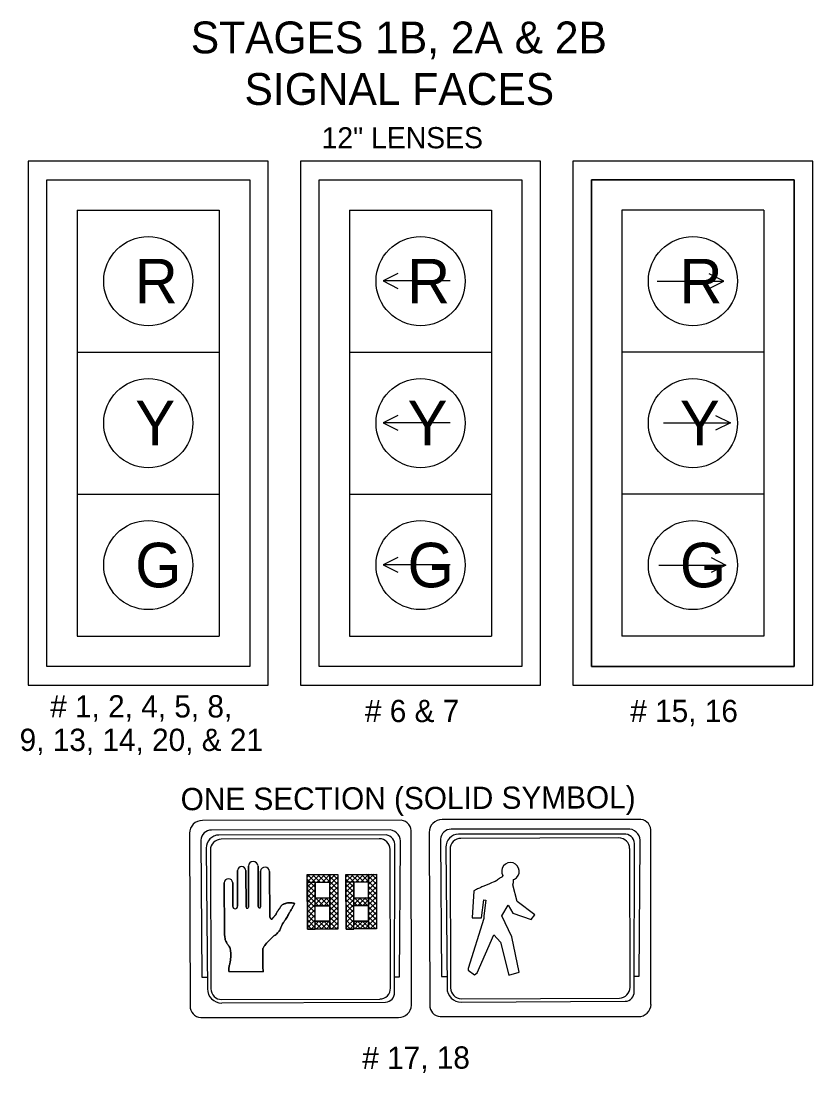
# Model space of a CAD drawing. Extents: x -218554 to 420030, y -566264 to -483460.
# Drawn here: x 418346.3 to 418495.6, y -565507.2 to -565308.8 of the extents above; entities that cross this region are included whole.
import ezdxf

# ---------------------------------------------------------------- set-up
doc = ezdxf.new("R2010")
doc.units = 0
for name, color, linetype in [('G-ANNO-STMP', 7, 'Continuous'), ('G-Border-Paper', 7, 'Continuous'), ('Level 1', 7, 'Continuous'), ('Level 61', 7, 'Continuous')]:
    doc.layers.add(name, color=color, linetype=linetype)

msp = doc.modelspace()

# ---------------------------------------------------------------- linework, layer by layer
at = {"layer": 'G-Border-Paper'}
for points in [[(418347.6, -565335.25), (418347.6, -565434.06), (418392.9, -565434.06), (418392.9, -565335.25), (418347.6, -565335.25)], [(418398.97, -565335.25), (418398.97, -565434.06), (418444.27, -565434.06), (418444.27, -565335.25), (418398.97, -565335.25)], [(418450.34, -565335.25), (418450.34, -565434.06), (418495.64, -565434.06), (418495.64, -565335.25), (418450.34, -565335.25)], [(418351.13, -565430.55), (418351.13, -565338.75), (418389.39, -565338.75), (418389.39, -565430.55), (418351.13, -565430.55)], [(418402.5, -565430.55), (418402.5, -565338.75), (418440.75, -565338.75), (418440.75, -565430.55), (418402.5, -565430.55)], [(418453.87, -565430.55), (418453.87, -565338.75), (418492.12, -565338.75), (418492.12, -565430.55), (418453.87, -565430.55)]]:
    msp.add_lwpolyline(points, dxfattribs=at)
at = {"layer": 'Level 1'}
for p, q in [((418417.97, -565459.55), (418380.47, -565459.58)), ((418463.18, -565459.4), (418425.68, -565459.43)), ((418378.02, -565462.02), (418378.16, -565494.56)), ((418415.91, -565461.37), (418382.19, -565461.41)), ((418419.88, -565494.44), (418419.84, -565461.93)), ((418423.23, -565461.86), (418423.37, -565494.4)), ((418461.11, -565461.22), (418427.39, -565461.26)), ((418460.34, -565462.18), (418428.79, -565462.18)), ((418465.08, -565494.28), (418465.05, -565461.77)), ((418415.14, -565462.33), (418383.59, -565462.34)), ((418381.19, -565464.82), (418381.41, -565491.33)), ((418416.71, -565492.01), (418416.75, -565464.45)), ((418426.39, -565464.66), (418426.62, -565491.18)), ((418461.92, -565491.86), (418461.95, -565464.29)), ((418390.97, -565468.19), (418390.99, -565475.85)), ((418390.99, -565475.85), (418390.97, -565468.19)), ((418387.1, -565475.79), (418387.07, -565469.05)), ((418387.07, -565469.05), (418387.1, -565475.79)), ((418388.67, -565469.06), (418388.7, -565475.9)), ((418388.7, -565475.9), (418388.67, -565469.06)), ((418389.16, -565475.93), (418389.13, -565468.21)), ((418389.13, -565468.21), (418389.16, -565475.93)), ((418391.45, -565475.89), (418391.43, -565469.16)), ((418391.43, -565469.16), (418391.45, -565475.89)), ((418393.14, -565469.21), (418393.17, -565477.87)), ((418393.17, -565477.87), (418393.14, -565469.21)), ((418400.23, -565472.19), (418402.62, -565469.78)), ((418400.23, -565470.27), (418400.71, -565469.79)), ((418400.23, -565471.23), (418401.66, -565469.79)), ((418400.28, -565469.79), (418401.79, -565471.29)), ((418401.24, -565469.79), (418402.75, -565471.28)), ((418402.08, -565471.29), (418403.58, -565469.78)), ((418402.2, -565469.79), (418403.7, -565471.28)), ((418403.04, -565471.28), (418404.53, -565469.78)), ((418403.15, -565469.78), (418406.01, -565472.62)), ((418403.99, -565471.28), (418405.49, -565469.77)), ((418404.11, -565469.78), (418406, -565471.66)), ((418405.07, -565469.78), (418406, -565470.7)), ((418407.52, -565470.25), (418408, -565469.77)), ((418407.53, -565471.2), (418408.96, -565469.76)), ((418407.53, -565472.16), (418409.91, -565469.76)), ((418407.58, -565469.77), (418409.08, -565471.26)), ((418408.54, -565469.76), (418410.04, -565471.26)), ((418409.38, -565471.26), (418410.87, -565469.76)), ((418409.49, -565469.76), (418411, -565471.26)), ((418410.33, -565471.26), (418411.83, -565469.75)), ((418410.45, -565469.76), (418413.3, -565472.59)), ((418411.29, -565471.25), (418412.78, -565469.75)), ((418411.41, -565469.75), (418413.3, -565471.63)), ((418412.36, -565469.75), (418413.3, -565470.68)), ((418384.61, -565480.66), (418384.58, -565471.34)), ((418384.58, -565471.34), (418384.61, -565480.66)), ((418386.18, -565471.35), (418386.19, -565475.8)), ((418386.19, -565475.8), (418386.18, -565471.35)), ((418400.23, -565470.69), (418401.73, -565472.19)), ((418400.23, -565471.65), (418401.74, -565473.14)), ((418400.24, -565473.14), (418401.73, -565471.64)), ((418404.5, -565471.73), (418406, -565470.22)), ((418404.51, -565472.68), (418406, -565471.18)), ((418404.51, -565472.08), (418406.01, -565473.57)), ((418404.51, -565473.64), (418406.01, -565472.13)), ((418407.52, -565470.67), (418409.03, -565472.16)), ((418407.53, -565473.12), (418409.03, -565471.61)), ((418407.53, -565471.62), (418409.03, -565473.12)), ((418411.8, -565471.7), (418413.29, -565470.2)), ((418411.8, -565472.66), (418413.3, -565471.15)), ((418411.8, -565472.05), (418413.31, -565473.55)), ((418411.81, -565473.61), (418413.3, -565472.11)), ((418439.32, -565470.67), (418439.32, -565470.67)), ((418400.24, -565474.1), (418401.74, -565472.59)), ((418400.24, -565472.61), (418403.33, -565475.68)), ((418400.24, -565475.06), (418401.74, -565473.55)), ((418400.24, -565473.56), (418402.38, -565475.69)), ((418403.44, -565475.68), (418406.01, -565473.09)), ((418404.39, -565475.68), (418406.01, -565474.05)), ((418404.51, -565473.04), (418406.01, -565474.53)), ((418404.51, -565473.99), (418406.02, -565475.49)), ((418407.53, -565472.58), (418410.63, -565475.66)), ((418407.53, -565473.54), (418409.67, -565475.66)), ((418407.54, -565474.07), (418409.03, -565472.57)), ((418407.54, -565475.03), (418409.03, -565473.53)), ((418407.54, -565475.99), (418409.36, -565474.16)), ((418407.55, -565476.94), (418410.31, -565474.16)), ((418409.04, -565474.16), (418411.81, -565474.15)), ((418409.78, -565475.66), (418411.27, -565474.15)), ((418410.08, -565474.16), (418411.59, -565475.65)), ((418410.73, -565475.66), (418413.3, -565473.07)), ((418411.04, -565474.16), (418413.32, -565476.42)), ((418411.69, -565475.65), (418413.31, -565474.02)), ((418411.8, -565473.01), (418413.31, -565474.5)), ((418411.81, -565473.97), (418413.31, -565475.46)), ((418400.24, -565474.52), (418401.75, -565476.01)), ((418400.25, -565476.97), (418403.02, -565474.18)), ((418400.25, -565476.01), (418402.06, -565474.19)), ((418400.25, -565475.48), (418401.75, -565476.97)), ((418401.74, -565474.19), (418404.51, -565474.18)), ((418401.75, -565475.69), (418404.52, -565475.68)), ((418402.48, -565475.69), (418403.98, -565474.18)), ((418402.79, -565474.18), (418404.29, -565475.68)), ((418403.74, -565474.18), (418406.02, -565476.44)), ((418404.52, -565476.51), (418406.02, -565475.01)), ((418404.52, -565475.91), (418406.02, -565477.4)), ((418404.52, -565477.47), (418406.02, -565475.96)), ((418407.54, -565474.49), (418409.04, -565475.99)), ((418407.54, -565475.45), (418409.05, -565476.95)), ((418409.04, -565475.66), (418411.81, -565475.65)), ((418411.81, -565475.88), (418413.32, -565477.37)), ((418411.82, -565476.48), (418413.31, -565474.98)), ((418411.82, -565477.44), (418413.31, -565475.94)), ((418400.25, -565477.93), (418401.75, -565476.42)), ((418400.25, -565476.43), (418401.75, -565477.93)), ((418400.25, -565477.39), (418402.97, -565480.08)), ((418400.26, -565478.88), (418401.75, -565477.38)), ((418402.88, -565480.08), (418406.02, -565476.92)), ((418403.84, -565480.08), (418406.03, -565477.88)), ((418404.52, -565476.86), (418406.03, -565478.36)), ((418404.53, -565477.82), (418406.03, -565479.31)), ((418407.54, -565476.41), (418409.05, -565477.9)), ((418407.55, -565477.9), (418409.04, -565476.4)), ((418407.55, -565478.86), (418409.05, -565477.35)), ((418407.55, -565477.36), (418410.26, -565480.06)), ((418410.17, -565480.06), (418413.32, -565476.89)), ((418411.13, -565480.06), (418413.32, -565477.85)), ((418411.82, -565476.84), (418413.32, -565478.33)), ((418411.82, -565477.79), (418413.33, -565479.29)), ((418400.26, -565479.84), (418401.76, -565478.33)), ((418400.26, -565478.35), (418402.01, -565480.09)), ((418400.26, -565479.3), (418401.05, -565480.09)), ((418400.97, -565480.09), (418402.46, -565478.59)), ((418401.92, -565480.09), (418403.42, -565478.58)), ((418402.42, -565478.59), (418403.92, -565480.08)), ((418403.37, -565478.58), (418404.88, -565480.08)), ((418404.33, -565478.58), (418405.84, -565480.07)), ((418404.79, -565480.08), (418406.03, -565478.83)), ((418405.75, -565480.07), (418406.03, -565479.79)), ((418407.55, -565478.32), (418409.3, -565480.06)), ((418407.55, -565479.28), (418408.35, -565480.06)), ((418407.56, -565479.81), (418409.05, -565478.31)), ((418408.26, -565480.07), (418409.76, -565478.56)), ((418409.22, -565480.06), (418410.71, -565478.56)), ((418409.71, -565478.56), (418411.22, -565480.05)), ((418410.67, -565478.56), (418412.17, -565480.05)), ((418411.63, -565478.55), (418413.13, -565480.05)), ((418412.09, -565480.05), (418413.32, -565478.81)), ((418413.04, -565480.05), (418413.33, -565479.76)), ((418385.48, -565488.1), (418391.92, -565488.12)), ((418391.89, -565488.11), (418385.51, -565488.14)), ((418391.92, -565488.12), (418391.89, -565488.11)), ((418384.12, -565494.02), (418415.01, -565493.86)), ((418429.32, -565493.87), (418460.22, -565493.7)), ((418380.14, -565496.75), (418417.48, -565496.75)), ((418425.34, -565496.59), (418462.69, -565496.59))]:
    msp.add_line(p, q, dxfattribs=at)
for points in [[(418380.18, -565463.31), (418380.34, -565489.16), (418381.43, -565489.16)], [(418413.81, -565463.03), (418384.01, -565463.13)], [(418416.7, -565489.11), (418417.67, -565489.11), (418417.83, -565463.93)], [(418425.38, -565463.15), (418425.55, -565489.01), (418426.63, -565489)], [(418459.02, -565462.87), (418429.22, -565462.98)], [(418461.9, -565488.96), (418462.88, -565488.95), (418463.04, -565463.77)], [(418381.97, -565465.19), (418382.06, -565491.33)], [(418415.95, -565491.21), (418415.86, -565465.07)], [(418427.18, -565465.03), (418427.27, -565491.18)], [(418461.16, -565491.06), (418461.07, -565464.91)], [(418404.51, -565474.18), (418404.5, -565471.28), (418401.73, -565471.29), (418401.74, -565474.19)], [(418411.81, -565474.15), (418411.8, -565471.25), (418409.03, -565471.26), (418409.04, -565474.16)], [(418431.65, -565472.88), (418431.37, -565477.95), (418433.11, -565477.94), (418433.55, -565474.59), (418433.95, -565474.6), (418433.53, -565477.58), (418433.53, -565478.08), (418430.58, -565487.5), (418430.58, -565487.86), (418431.77, -565488.68), (418432.28, -565488.32), (418435.42, -565481.19), (418436.71, -565482.52), (418438.24, -565488.8), (418440.21, -565488.2), (418438.81, -565481.55), (418436.92, -565477.61), (418438.15, -565475.59), (418439.02, -565477.05), (418442.51, -565478.28), (418443.2, -565477.4), (418439.87, -565474.9), (418439, -565471.74), (418439.14, -565471.27), (418439.15, -565470.76), (418439.32, -565470.67)], [(418404.52, -565475.68), (418404.53, -565478.58), (418401.76, -565478.59), (418401.75, -565475.69)], [(418411.81, -565475.65), (418411.82, -565478.55), (418409.05, -565478.56), (418409.04, -565475.66)], [(418384.12, -565493.37), (418413.92, -565493.27)], [(418429.32, -565493.21), (418459.12, -565493.11)]]:
    msp.add_lwpolyline(points, dxfattribs=at)
for points in [[(418400.23, -565469.79), (418406, -565469.77), (418406.03, -565480.07), (418400.26, -565480.09)], [(418400.23, -565469.79), (418404.5, -565469.79), (418404.5, -565471.28), (418400.23, -565471.28)], [(418404.5, -565469.79), (418406.03, -565469.79), (418406.03, -565480.07), (418404.51, -565480.07)], [(418407.52, -565469.77), (418413.29, -565469.75), (418413.33, -565480.05), (418407.56, -565480.07)], [(418407.52, -565469.77), (418411.8, -565469.76), (418411.8, -565471.25), (418407.52, -565471.26)], [(418411.8, -565469.76), (418413.32, -565469.76), (418413.33, -565480.05), (418411.8, -565480.05)], [(418400.26, -565480.09), (418401.74, -565480.09), (418401.73, -565471.29), (418400.26, -565471.29)], [(418407.56, -565480.07), (418409.03, -565480.07), (418409.03, -565471.26), (418407.55, -565471.26)], [(418409.04, -565474.16), (418411.81, -565474.16), (418411.81, -565475.65), (418409.04, -565475.66)], [(418401.74, -565474.19), (418404.52, -565474.19), (418404.52, -565475.68), (418401.74, -565475.68)], [(418401.76, -565478.59), (418404.51, -565478.59), (418404.51, -565480.07), (418401.76, -565480.08)], [(418409.05, -565478.56), (418411.8, -565478.56), (418411.8, -565480.05), (418409.05, -565480.05)]]:
    msp.add_lwpolyline(points, close=True, dxfattribs=at)
for centre, radius, start, end in [((418380.47, -565462.03), 2.44, 89.8211, 179.8211), ((418417.72, -565461.68), 2.14, 353.227, 83.227), ((418425.67, -565461.87), 2.44, 89.8211, 179.8211), ((418462.92, -565461.52), 2.14, 353.227, 83.227), ((418382.13, -565463.37), 1.95, 88.3219, 178.3219), ((418415.59, -565463.61), 2.26, 351.9574, 81.9574), ((418427.34, -565463.21), 1.95, 88.3219, 178.3219), ((418428.83, -565464.62), 2.44, 90.9287, 180.9287), ((418460.09, -565464.04), 1.88, 352.2729, 82.2729), ((418460.8, -565463.46), 2.26, 351.9574, 81.9574), ((418383.63, -565464.78), 2.44, 90.9287, 180.9287), ((418384.02, -565465.18), 2.04, 90.1989, 180.1989), ((418413.82, -565465.08), 2.04, 0.1989, 90.1989), ((418414.88, -565464.2), 1.88, 352.2729, 82.2729), ((418429.22, -565465.02), 2.04, 90.1989, 180.1989), ((418459.02, -565464.92), 2.04, 0.1989, 90.1989), ((418390.05, -565468.25), 0.921, 4.0989, 177.4457), ((418390.05, -565468.25), 0.921, 4.0989, 177.4457), ((418438.58, -565469.19), 1.66, 296.6638, 209.0011), ((418387.87, -565469.1), 0.801, 2.8665, 176.2133), ((418387.87, -565469.1), 0.801, 2.8665, 176.2133), ((418392.28, -565469.24), 0.857, 1.6765, 175.0233), ((418392.28, -565469.24), 0.857, 1.6765, 175.0233), ((418385.38, -565471.39), 0.801, 2.8665, 176.2133), ((418385.38, -565471.39), 0.801, 2.8665, 176.2133), ((418386.65, -565475.79), 0.45, 180.1989, 0.1989), ((418386.65, -565475.79), 0.45, 180.1989, 0.1989), ((418388.93, -565475.92), 0.231, 175.6215, 355.6215), ((418388.93, -565475.92), 0.231, 175.6215, 355.6215), ((418391.22, -565475.87), 0.234, 175.0942, 355.0942), ((418391.22, -565475.87), 0.234, 175.0942, 355.0942), ((418384.11, -565491.33), 2.7, 180.1989, 270.1989), ((418384.11, -565491.33), 2.04, 180.1989, 270.1989), ((418413.91, -565491.22), 2.04, 270.1989, 0.1989), ((418414.94, -565492.09), 1.77, 272.3085, 2.3085), ((418429.31, -565491.17), 2.7, 180.1989, 270.1989), ((418429.31, -565491.17), 2.04, 180.1989, 270.1989), ((418459.11, -565491.07), 2.04, 270.1989, 0.1989), ((418460.15, -565491.93), 1.77, 272.3085, 2.3085), ((418380.25, -565494.67), 2.09, 176.9799, 266.9799), ((418417.52, -565494.39), 2.36, 268.9594, 358.9594), ((418425.45, -565494.51), 2.09, 176.9799, 266.9799), ((418462.73, -565494.24), 2.36, 268.9594, 358.9594)]:
    msp.add_arc(centre, radius, start, end, dxfattribs=at)
for points in [[(418437.12, -565469.99), (418436.93, -565470.27), (418436.66, -565470.41), (418436.34, -565470.64), (418435.98, -565470.91), (418434.65, -565471.52), (418434.01, -565471.79), (418433.38, -565472.04), (418432.54, -565472.44), (418432.14, -565472.59), (418431.65, -565472.88)], [(418393.17, -565477.87), (418393.23, -565477.88), (418393.32, -565478.06), (418393.43, -565478.19), (418393.5, -565478.21), (418393.61, -565478.19), (418393.67, -565478.1), (418393.87, -565477.88), (418394.03, -565477.7), (418394.11, -565477.57), (418394.2, -565477.46), (418394.36, -565477.26), (418394.44, -565477.08), (418394.58, -565476.84), (418394.66, -565476.7), (418394.82, -565476.46), (418394.99, -565476.24), (418395.12, -565476.02), (418395.28, -565475.8), (418395.41, -565475.64), (418395.61, -565475.46), (418395.85, -565475.37), (418395.98, -565475.3), (418396.18, -565475.24), (418396.36, -565475.17), (418396.63, -565475.13), (418396.85, -565475.13), (418397.13, -565475.12), (418397.4, -565475.15), (418397.71, -565475.19), (418397.8, -565475.23), (418397.82, -565475.3), (418397.69, -565475.59), (418397.6, -565475.74), (418397.51, -565475.9), (418397.42, -565476.07), (418397.38, -565476.18), (418397.2, -565476.47), (418396.94, -565476.87), (418396.59, -565477.52), (418396.15, -565478.25), (418395.8, -565478.76), (418395.6, -565479.09), (418395.42, -565479.4), (418395.32, -565479.65), (418395.27, -565479.77), (418395.07, -565480.31), (418394.77, -565480.68), (418394.52, -565480.95), (418394.17, -565481.22), (418393.95, -565481.37), (418393.38, -565481.95), (418392.87, -565482.44), (418392.54, -565482.77), (418392.25, -565483.15), (418392.11, -565483.31), (418391.99, -565483.55), (418391.86, -565483.77), (418391.86, -565484.26), (418391.84, -565484.69), (418391.84, -565485.09), (418391.87, -565485.62), (418391.87, -565486.13), (418391.87, -565486.95), (418391.89, -565487.61), (418391.92, -565487.85), (418391.92, -565488.03), (418391.92, -565488.12)], [(418391.92, -565488.12), (418391.92, -565488.03), (418391.92, -565487.85), (418391.89, -565487.61), (418391.87, -565486.95), (418391.87, -565486.13), (418391.87, -565485.62), (418391.84, -565485.09), (418391.84, -565484.69), (418391.86, -565484.26), (418391.86, -565483.77), (418391.99, -565483.55), (418392.11, -565483.31), (418392.25, -565483.15), (418392.54, -565482.77), (418392.87, -565482.44), (418393.38, -565481.95), (418393.95, -565481.37), (418394.17, -565481.22), (418394.52, -565480.95), (418394.77, -565480.68), (418395.07, -565480.31), (418395.27, -565479.77), (418395.32, -565479.65), (418395.42, -565479.4), (418395.6, -565479.09), (418395.8, -565478.76), (418396.15, -565478.25), (418396.59, -565477.52), (418396.94, -565476.87), (418397.2, -565476.47), (418397.38, -565476.18), (418397.42, -565476.07), (418397.51, -565475.9), (418397.6, -565475.74), (418397.69, -565475.59), (418397.82, -565475.3), (418397.8, -565475.23), (418397.71, -565475.19), (418397.4, -565475.15), (418397.13, -565475.12), (418396.85, -565475.13), (418396.63, -565475.13), (418396.36, -565475.17), (418396.18, -565475.24), (418395.98, -565475.3), (418395.85, -565475.37), (418395.61, -565475.46), (418395.41, -565475.64), (418395.28, -565475.8), (418395.12, -565476.02), (418394.99, -565476.24), (418394.82, -565476.46), (418394.66, -565476.7), (418394.58, -565476.84), (418394.44, -565477.08), (418394.36, -565477.26), (418394.2, -565477.46), (418394.11, -565477.57), (418394.03, -565477.7), (418393.87, -565477.88), (418393.67, -565478.1), (418393.61, -565478.19), (418393.5, -565478.21), (418393.43, -565478.19), (418393.32, -565478.06), (418393.23, -565477.88), (418393.17, -565477.87)], [(418385.48, -565488.1), (418385.48, -565487.74), (418385.5, -565487.15), (418385.67, -565486.53), (418385.76, -565485.82), (418385.82, -565485.42), (418385.82, -565484.65), (418385.75, -565484.01), (418385.68, -565483.68), (418385.35, -565483.12), (418384.99, -565482.57), (418384.79, -565482.11), (418384.7, -565481.62), (418384.64, -565481.24), (418384.63, -565481), (418384.61, -565480.66)], [(418384.61, -565480.66), (418384.63, -565481), (418384.64, -565481.24), (418384.7, -565481.62), (418384.79, -565482.11), (418384.99, -565482.57), (418385.35, -565483.12), (418385.68, -565483.68), (418385.75, -565484.01), (418385.82, -565484.65), (418385.82, -565485.42), (418385.76, -565485.82), (418385.67, -565486.53), (418385.5, -565487.15), (418385.48, -565487.74), (418385.48, -565488.1)]]:
    msp.add_spline(points, degree=3, dxfattribs=at)
at = {"layer": 'Level 61'}
for p, q in [((418356.87, -565344.48), (418383.65, -565344.48)), ((418356.87, -565344.48), (418356.87, -565371.26)), ((418383.65, -565344.48), (418383.65, -565371.26)), ((418408.24, -565344.48), (418435.02, -565344.48)), ((418408.24, -565344.48), (418408.24, -565371.26)), ((418435.02, -565344.48), (418435.02, -565371.26)), ((418486.39, -565344.48), (418459.61, -565344.48)), ((418459.61, -565344.48), (418459.61, -565371.26)), ((418486.39, -565344.48), (418486.39, -565371.26)), ((418427.18, -565357.83), (418414.56, -565357.83)), ((418466.23, -565357.87), (418478.85, -565357.87)), ((418356.87, -565371.26), (418383.65, -565371.26)), ((418356.87, -565371.26), (418356.87, -565398.04)), ((418383.65, -565371.26), (418383.65, -565398.04)), ((418408.24, -565371.26), (418435.02, -565371.26)), ((418408.24, -565371.26), (418408.24, -565398.04)), ((418435.02, -565371.26), (418435.02, -565398.04)), ((418486.39, -565371.26), (418459.61, -565371.26)), ((418459.61, -565371.26), (418459.61, -565398.04)), ((418486.39, -565371.26), (418486.39, -565398.04)), ((418427.18, -565384.61), (418414.56, -565384.61)), ((418467.45, -565384.61), (418480.07, -565384.61)), ((418356.87, -565398.04), (418383.65, -565398.04)), ((418356.87, -565398.04), (418356.87, -565424.81)), ((418383.65, -565398.04), (418383.65, -565424.81)), ((418408.24, -565398.04), (418435.02, -565398.04)), ((418408.24, -565398.04), (418408.24, -565424.81)), ((418435.02, -565398.04), (418435.02, -565424.81)), ((418486.39, -565398.04), (418459.61, -565398.04)), ((418459.61, -565398.04), (418459.61, -565424.81)), ((418486.39, -565398.04), (418486.39, -565424.81)), ((418427.18, -565411.39), (418414.56, -565411.39)), ((418466.59, -565411.42), (418479.21, -565411.42)), ((418356.87, -565424.81), (418383.65, -565424.81)), ((418408.24, -565424.81), (418435.02, -565424.81)), ((418486.39, -565424.81), (418459.61, -565424.81))]:
    msp.add_line(p, q, dxfattribs=at)
for points in [[(418351.13, -565338.75), (418389.39, -565338.75), (418389.39, -565430.55), (418351.13, -565430.55)], [(418402.5, -565338.75), (418440.75, -565338.75), (418440.75, -565430.55), (418402.5, -565430.55)], [(418492.12, -565338.75), (418453.87, -565338.75), (418453.87, -565430.55), (418492.12, -565430.55)]]:
    msp.add_lwpolyline(points, close=True, dxfattribs=at)
for points in [[(418417.36, -565356.43), (418414.56, -565357.83), (418417.36, -565359.24)], [(418476.05, -565359.27), (418478.85, -565357.87), (418476.05, -565356.47)], [(418417.36, -565383.21), (418414.56, -565384.61), (418417.36, -565386.01)], [(418477.27, -565383.21), (418480.07, -565384.61), (418477.27, -565386.01)], [(418417.36, -565409.99), (418414.56, -565411.39), (418417.36, -565412.79)], [(418476.41, -565410.02), (418479.21, -565411.42), (418476.41, -565412.83)]]:
    msp.add_lwpolyline(points, dxfattribs=at)
for centre in [(418370.26, -565357.87), (418421.63, -565357.87), (418473, -565357.87), (418370.26, -565384.65), (418421.63, -565384.65), (418473, -565384.65), (418370.26, -565411.42), (418421.63, -565411.42), (418473, -565411.42)]:
    msp.add_circle(centre, 8.41, dxfattribs=at)

# ---------------------------------------------------------------- texts
at = {"layer": 'G-ANNO-STMP'}
for s, p in [('# 1, 2, 4, 5, 8, ', (418351.75, -565440.17)), ('# 6 & 7', (418411.12, -565441.04)), ('# 15, 16', (418461.18, -565441.04)), ('9, 13, 14, 20, & 21', (418345.99, -565446.49))]:
    msp.add_text(s, height=4.2, dxfattribs=at).set_placement(p)
for s, p in [('ONE SECTION (SOLID SYMBOL)', (418376.37, -565457.67)), ('# 17, 18', (418410.63, -565506.49))]:
    msp.add_text(s, height=4.2, rotation=0.2455, dxfattribs=at).set_placement(p)
at = {"layer": 'Level 61'}
for s, height, p in [('STAGES 1B, 2A & 2B', 6, (418378.28, -565314.91)), ('SIGNAL FACES', 6, (418388.41, -565324.63)), ('R', 8.41, (418367.71, -565362.08)), ('R', 8.41, (418419.08, -565362.08)), ('R', 8.41, (418470.45, -565362.08)), ('Y', 8.41, (418367.81, -565388.85)), ('Y', 8.41, (418419.18, -565388.85)), ('Y', 8.41, (418470.55, -565388.85)), ('G', 8.41, (418367.79, -565415.63)), ('G', 8.41, (418419.16, -565415.63)), ('G', 8.41, (418470.53, -565415.63))]:
    msp.add_text(s, height=height, dxfattribs=at).set_placement(p)
msp.add_text('12" LENSES', height=4, rotation=0.072, dxfattribs=at).set_placement((418402.95, -565332.85))

doc.saveas('drawing.dxf')
